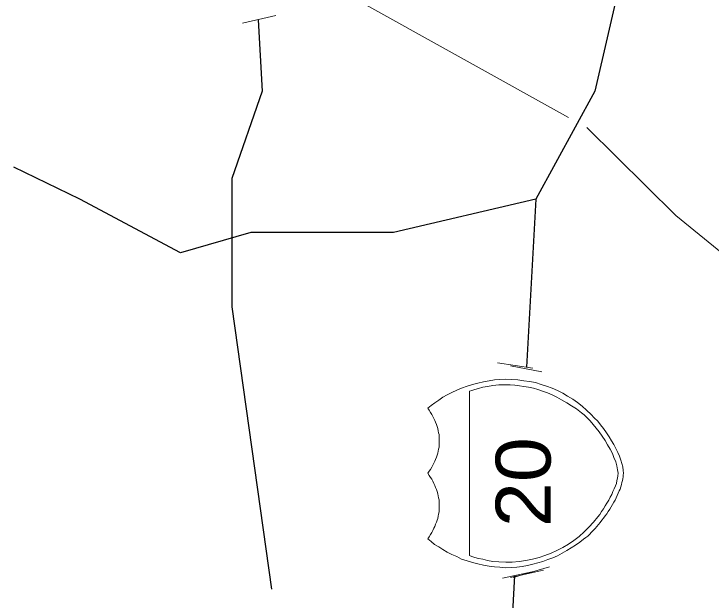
# Model space of a CAD drawing. Extents: x 2363323 to 2367082, y 6956018 to 6980837.
# Drawn here: x 2365996.5 to 2366061.2, y 6980473 to 6980527.4 of the extents above; entities that cross this region are included whole.
import ezdxf

# ---------------------------------------------------------------- set-up
doc = ezdxf.new("R2010")
doc.units = 0
doc.header["$LTSCALE"] = 4.1
doc.layers.add('62', color=7, linetype='Continuous', lineweight=13)
doc.layers.add('63', color=7, linetype='Continuous', lineweight=13)

msp = doc.modelspace()

# ---------------------------------------------------------------- linework, layer by layer
at = {"layer": '62'}
for p, q in [((2366026.698, 6980529.676), (2366047.962, 6980517.816)), ((2366017.744, 6980526.572), (2366020.826, 6980527.268)), ((2366041.396, 6980495.044), (2366044.656, 6980494.55)), ((2366042.586, 6980494.773), (2366045.489, 6980494.212)), ((2366041.846, 6980475.063), (2366044.612, 6980475.672)), ((2366042.588, 6980475.132), (2366045.67, 6980475.828)), ((2366042.834, 6980475.13), (2366046.209, 6980476.12))]:
    msp.add_line(p, q, dxfattribs=at)
at = {"layer": '62', "lineweight": 25}
for p, q in [((2366002.646, 6980510.235), (2365996.546, 6980513.204)), ((2366044.949, 6980510.235), (2366044.073, 6980494.64))]:
    msp.add_line(p, q, dxfattribs=at)
for points in [[(2366048.01, 6980685.208), (2366049.539, 6980677.378), (2366050.418, 6980667.388), (2366051.476, 6980653.346), (2366051.474, 6980643.356), (2366052.352, 6980636.2), (2366055.164, 6980631.206), (2366057.122, 6980621.192), (2366056.064, 6980607.15), (2366055.164, 6980594.301), (2366054.309, 6980580.237), (2366057.123, 6980558.096), (2366054.309, 6980537.146), (2366050.416, 6980520.246), (2366044.949, 6980510.235), (2366031.738, 6980507.152), (2366018.51, 6980507.151), (2366011.984, 6980505.261), (2366002.646, 6980510.235)], [(2366019.184, 6980526.885), (2366019.568, 6980520.246), (2366016.755, 6980512.146), (2366016.754, 6980500.244), (2366020.445, 6980474.05)], [(2366042.97, 6980475.31), (2366042.183, 6980460.999), (2366034.551, 6980446.35), (2366022.334, 6980438.454)]]:
    msp.add_lwpolyline(points, dxfattribs=at)
at = {"layer": '62'}
for points in [[(2366049.676, 6980516.892), (2366057.932, 6980508.726), (2366065.266, 6980502.741), (2366077.871, 6980489.824), (2366091.302, 6980478.192)], [(2366035.408, 6980485.548), (2366035.498, 6980485.728), (2366035.588, 6980485.93), (2366035.655, 6980486.088), (2366035.745, 6980486.292), (2366035.79, 6980486.493), (2366035.859, 6980486.673), (2366035.88, 6980486.853), (2366035.925, 6980487.054), (2366035.972, 6980487.236), (2366035.994, 6980487.436), (2366035.994, 6980487.618), (2366035.992, 6980487.822), (2366035.992, 6980488.002), (2366035.992, 6980488.182), (2366035.97, 6980488.407), (2366035.926, 6980488.564), (2366035.88, 6980488.744), (2366035.858, 6980488.948), (2366035.79, 6980489.15), (2366035.745, 6980489.331), (2366035.656, 6980489.532), (2366035.589, 6980489.712), (2366035.499, 6980489.89), (2366035.408, 6980490.074), (2366035.294, 6980490.252), (2366035.182, 6980490.454), (2366035.068, 6980490.658), (2366034.934, 6980490.838), (2366035.248, 6980491.107), (2366035.566, 6980491.354), (2366035.948, 6980491.602), (2366036.33, 6980491.85), (2366036.738, 6980492.073), (2366037.164, 6980492.3), (2366037.614, 6980492.502), (2366038.064, 6980492.704), (2366038.582, 6980492.884), (2366039.076, 6980493.04), (2366039.573, 6980493.178), (2366040.089, 6980493.29), (2366040.608, 6980493.38), (2366041.124, 6980493.47), (2366041.619, 6980493.492), (2366042.159, 6980493.537), (2366042.7, 6980493.492), (2366043.284, 6980493.47), (2366043.826, 6980493.38), (2366044.364, 6980493.312), (2366044.904, 6980493.224), (2366045.444, 6980493.042), (2366045.939, 6980492.884), (2366046.456, 6980492.704), (2366046.953, 6980492.48), (2366047.446, 6980492.232), (2366047.896, 6980491.964), (2366048.37, 6980491.692), (2366048.82, 6980491.356), (2366049.246, 6980491.017), (2366049.652, 6980490.657), (2366050.079, 6980490.252), (2366050.372, 6980489.96), (2366050.686, 6980489.644), (2366050.956, 6980489.284), (2366051.226, 6980488.948), (2366051.496, 6980488.564), (2366051.744, 6980488.18), (2366051.97, 6980487.822), (2366052.196, 6980487.46), (2366052.374, 6980487.1), (2366052.554, 6980486.74), (2366052.712, 6980486.38), (2366052.846, 6980486.022), (2366052.914, 6980485.706), (2366053.006, 6980485.39), (2366053.049, 6980485.076), (2366053.072, 6980484.807)], [(2366053.072, 6980484.807), (2366053.05, 6980484.624), (2366053.05, 6980484.468), (2366053.004, 6980484.288), (2366052.982, 6980484.132), (2366052.936, 6980483.95), (2366052.892, 6980483.77), (2366052.824, 6980483.546), (2366052.756, 6980483.343), (2366052.668, 6980483.164), (2366052.578, 6980482.96), (2366052.486, 6980482.736), (2366052.396, 6980482.533), (2366052.306, 6980482.308), (2366052.196, 6980482.13), (2366052.06, 6980481.903), (2366051.946, 6980481.678), (2366051.812, 6980481.476), (2366051.654, 6980481.25), (2366051.52, 6980481.05), (2366051.386, 6980480.847), (2366051.228, 6980480.643), (2366051.069, 6980480.442), (2366050.913, 6980480.238), (2366050.756, 6980480.058), (2366050.596, 6980479.856), (2366050.439, 6980479.676), (2366050.259, 6980479.496), (2366050.102, 6980479.338), (2366049.922, 6980479.136), (2366049.766, 6980478.978), (2366049.584, 6980478.843), (2366049.382, 6980478.686), (2366049.022, 6980478.414), (2366048.616, 6980478.123), (2366048.213, 6980477.876), (2366047.808, 6980477.628), (2366047.38, 6980477.382), (2366046.953, 6980477.156), (2366046.524, 6980476.954), (2366046.052, 6980476.796), (2366045.602, 6980476.616), (2366045.13, 6980476.48), (2366044.656, 6980476.368), (2366044.184, 6980476.256), (2366043.689, 6980476.143), (2366043.196, 6980476.098), (2366042.654, 6980476.052), (2366042.16, 6980476.032), (2366041.618, 6980476.076), (2366041.124, 6980476.122), (2366040.606, 6980476.188), (2366040.089, 6980476.28), (2366039.573, 6980476.39), (2366039.076, 6980476.524), (2366038.582, 6980476.682), (2366038.064, 6980476.842), (2366037.616, 6980477.066), (2366037.164, 6980477.27), (2366036.738, 6980477.493), (2366036.33, 6980477.718), (2366035.948, 6980477.986), (2366035.565, 6980478.19), (2366035.25, 6980478.459), (2366034.934, 6980478.73), (2366035.068, 6980478.91), (2366035.182, 6980479.113), (2366035.294, 6980479.316), (2366035.408, 6980479.497), (2366035.498, 6980479.698), (2366035.588, 6980479.878), (2366035.656, 6980480.08), (2366035.745, 6980480.262), (2366035.79, 6980480.44), (2366035.858, 6980480.62), (2366035.88, 6980480.823), (2366035.926, 6980481.003), (2366035.97, 6980481.23), (2366035.992, 6980481.386), (2366035.992, 6980481.566), (2366035.994, 6980481.792), (2366035.992, 6980481.972), (2366035.994, 6980482.149), (2366035.972, 6980482.353), (2366035.926, 6980482.533), (2366035.882, 6980482.712), (2366035.858, 6980482.893), (2366035.792, 6980483.12), (2366035.746, 6980483.3), (2366035.655, 6980483.478), (2366035.589, 6980483.658), (2366035.498, 6980483.86), (2366035.408, 6980484.063), (2366035.294, 6980484.244), (2366035.181, 6980484.423), (2366035.07, 6980484.603), (2366034.934, 6980484.806), (2366035.07, 6980484.986), (2366035.182, 6980485.166), (2366035.295, 6980485.368), (2366035.408, 6980485.548)]]:
    msp.add_lwpolyline(points, dxfattribs=at)
msp.add_lwpolyline([(2366038.786, 6980492.412), (2366038.786, 6980477.178), (2366039.01, 6980477.088), (2366039.302, 6980476.998), (2366039.618, 6980476.908), (2366040.023, 6980476.82), (2366040.473, 6980476.706), (2366040.966, 6980476.616), (2366041.53, 6980476.572), (2366042.16, 6980476.57), (2366042.768, 6980476.57), (2366043.396, 6980476.616), (2366044.026, 6980476.704), (2366044.634, 6980476.842), (2366045.242, 6980476.998), (2366045.783, 6980477.178), (2366046.366, 6980477.382), (2366046.908, 6980477.652), (2366047.446, 6980477.92), (2366047.964, 6980478.213), (2366048.483, 6980478.573), (2366048.956, 6980478.933), (2366049.426, 6980479.36), (2366049.876, 6980479.81), (2366050.283, 6980480.26), (2366050.688, 6980480.756), (2366050.89, 6980480.98), (2366051.046, 6980481.25), (2366051.228, 6980481.498), (2366051.386, 6980481.789), (2366051.542, 6980482.038), (2366051.723, 6980482.308), (2366051.856, 6980482.58), (2366051.992, 6980482.848), (2366052.104, 6980483.118), (2366052.216, 6980483.366), (2366052.33, 6980483.637), (2366052.419, 6980483.86), (2366052.464, 6980484.13), (2366052.533, 6980484.354), (2366052.556, 6980484.58), (2366052.576, 6980484.807), (2366052.533, 6980485.12), (2366052.464, 6980485.503), (2366052.353, 6980485.864), (2366052.196, 6980486.268), (2366052.06, 6980486.65), (2366051.834, 6980487.054), (2366051.609, 6980487.438), (2366051.386, 6980487.844), (2366051.114, 6980488.25), (2366050.822, 6980488.634), (2366050.553, 6980488.992), (2366050.259, 6980489.33), (2366049.989, 6980489.668), (2366049.72, 6980489.96), (2366049.426, 6980490.23), (2366049.179, 6980490.41), (2366048.706, 6980490.77), (2366048.256, 6980491.062), (2366047.808, 6980491.354), (2366047.336, 6980491.623), (2366046.908, 6980491.874), (2366046.456, 6980492.076), (2366046.03, 6980492.254), (2366045.58, 6980492.414), (2366045.13, 6980492.57), (2366044.726, 6980492.704), (2366044.274, 6980492.794), (2366043.846, 6980492.862), (2366043.419, 6980492.93), (2366042.992, 6980492.974), (2366042.566, 6980492.997), (2366042.159, 6980492.997), (2366041.53, 6980492.997), (2366040.966, 6980492.952), (2366040.473, 6980492.862), (2366040.023, 6980492.794), (2366039.618, 6980492.682), (2366039.303, 6980492.57), (2366039.009, 6980492.48)], close=True, dxfattribs=at)
at = {"layer": '63'}
for p, q in [((2366026.698, 6980529.676), (2366047.962, 6980517.816)), ((2366017.744, 6980526.572), (2366020.826, 6980527.268)), ((2366041.396, 6980495.044), (2366044.656, 6980494.55)), ((2366042.586, 6980494.773), (2366045.489, 6980494.212)), ((2366041.846, 6980475.063), (2366044.612, 6980475.672)), ((2366042.588, 6980475.132), (2366045.67, 6980475.828)), ((2366042.834, 6980475.13), (2366046.209, 6980476.12))]:
    msp.add_line(p, q, dxfattribs=at)
at = {"layer": '63', "lineweight": 25}
for p, q in [((2366002.646, 6980510.235), (2365996.546, 6980513.204)), ((2366044.949, 6980510.235), (2366044.073, 6980494.64))]:
    msp.add_line(p, q, dxfattribs=at)
for points in [[(2366048.01, 6980685.208), (2366049.539, 6980677.378), (2366050.418, 6980667.388), (2366051.476, 6980653.346), (2366051.474, 6980643.356), (2366052.352, 6980636.2), (2366055.164, 6980631.206), (2366057.122, 6980621.192), (2366056.064, 6980607.15), (2366055.164, 6980594.301), (2366054.309, 6980580.237), (2366057.123, 6980558.096), (2366054.309, 6980537.146), (2366050.416, 6980520.246), (2366044.949, 6980510.235), (2366031.738, 6980507.152), (2366018.51, 6980507.151), (2366011.984, 6980505.261), (2366002.646, 6980510.235)], [(2366019.184, 6980526.885), (2366019.568, 6980520.246), (2366016.755, 6980512.146), (2366016.754, 6980500.244), (2366020.445, 6980474.05)], [(2366042.97, 6980475.31), (2366042.183, 6980460.999), (2366034.551, 6980446.35), (2366022.334, 6980438.454)]]:
    msp.add_lwpolyline(points, dxfattribs=at)
at = {"layer": '63'}
for points in [[(2366049.676, 6980516.892), (2366057.932, 6980508.726), (2366065.266, 6980502.741), (2366077.871, 6980489.824), (2366091.302, 6980478.192)], [(2366035.408, 6980485.548), (2366035.498, 6980485.728), (2366035.588, 6980485.93), (2366035.655, 6980486.088), (2366035.745, 6980486.292), (2366035.79, 6980486.493), (2366035.859, 6980486.673), (2366035.88, 6980486.853), (2366035.925, 6980487.054), (2366035.972, 6980487.236), (2366035.994, 6980487.436), (2366035.994, 6980487.618), (2366035.992, 6980487.822), (2366035.992, 6980488.002), (2366035.992, 6980488.182), (2366035.97, 6980488.407), (2366035.926, 6980488.564), (2366035.88, 6980488.744), (2366035.858, 6980488.948), (2366035.79, 6980489.15), (2366035.745, 6980489.331), (2366035.656, 6980489.532), (2366035.589, 6980489.712), (2366035.499, 6980489.89), (2366035.408, 6980490.074), (2366035.294, 6980490.252), (2366035.182, 6980490.454), (2366035.068, 6980490.658), (2366034.934, 6980490.838), (2366035.248, 6980491.107), (2366035.566, 6980491.354), (2366035.948, 6980491.602), (2366036.33, 6980491.85), (2366036.738, 6980492.073), (2366037.164, 6980492.3), (2366037.614, 6980492.502), (2366038.064, 6980492.704), (2366038.582, 6980492.884), (2366039.076, 6980493.04), (2366039.573, 6980493.178), (2366040.089, 6980493.29), (2366040.608, 6980493.38), (2366041.124, 6980493.47), (2366041.619, 6980493.492), (2366042.159, 6980493.537), (2366042.7, 6980493.492), (2366043.284, 6980493.47), (2366043.826, 6980493.38), (2366044.364, 6980493.312), (2366044.904, 6980493.224), (2366045.444, 6980493.042), (2366045.939, 6980492.884), (2366046.456, 6980492.704), (2366046.953, 6980492.48), (2366047.446, 6980492.232), (2366047.896, 6980491.964), (2366048.37, 6980491.692), (2366048.82, 6980491.356), (2366049.246, 6980491.017), (2366049.652, 6980490.657), (2366050.079, 6980490.252), (2366050.372, 6980489.96), (2366050.686, 6980489.644), (2366050.956, 6980489.284), (2366051.226, 6980488.948), (2366051.496, 6980488.564), (2366051.744, 6980488.18), (2366051.97, 6980487.822), (2366052.196, 6980487.46), (2366052.374, 6980487.1), (2366052.554, 6980486.74), (2366052.712, 6980486.38), (2366052.846, 6980486.022), (2366052.914, 6980485.706), (2366053.006, 6980485.39), (2366053.049, 6980485.076), (2366053.072, 6980484.807)], [(2366053.072, 6980484.807), (2366053.05, 6980484.624), (2366053.05, 6980484.468), (2366053.004, 6980484.288), (2366052.982, 6980484.132), (2366052.936, 6980483.95), (2366052.892, 6980483.77), (2366052.824, 6980483.546), (2366052.756, 6980483.343), (2366052.668, 6980483.164), (2366052.578, 6980482.96), (2366052.486, 6980482.736), (2366052.396, 6980482.533), (2366052.306, 6980482.308), (2366052.196, 6980482.13), (2366052.06, 6980481.903), (2366051.946, 6980481.678), (2366051.812, 6980481.476), (2366051.654, 6980481.25), (2366051.52, 6980481.05), (2366051.386, 6980480.847), (2366051.228, 6980480.643), (2366051.069, 6980480.442), (2366050.913, 6980480.238), (2366050.756, 6980480.058), (2366050.596, 6980479.856), (2366050.439, 6980479.676), (2366050.259, 6980479.496), (2366050.102, 6980479.338), (2366049.922, 6980479.136), (2366049.766, 6980478.978), (2366049.584, 6980478.843), (2366049.382, 6980478.686), (2366049.022, 6980478.414), (2366048.616, 6980478.123), (2366048.213, 6980477.876), (2366047.808, 6980477.628), (2366047.38, 6980477.382), (2366046.953, 6980477.156), (2366046.524, 6980476.954), (2366046.052, 6980476.796), (2366045.602, 6980476.616), (2366045.13, 6980476.48), (2366044.656, 6980476.368), (2366044.184, 6980476.256), (2366043.689, 6980476.143), (2366043.196, 6980476.098), (2366042.654, 6980476.052), (2366042.16, 6980476.032), (2366041.618, 6980476.076), (2366041.124, 6980476.122), (2366040.606, 6980476.188), (2366040.089, 6980476.28), (2366039.573, 6980476.39), (2366039.076, 6980476.524), (2366038.582, 6980476.682), (2366038.064, 6980476.842), (2366037.616, 6980477.066), (2366037.164, 6980477.27), (2366036.738, 6980477.493), (2366036.33, 6980477.718), (2366035.948, 6980477.986), (2366035.565, 6980478.19), (2366035.25, 6980478.459), (2366034.934, 6980478.73), (2366035.068, 6980478.91), (2366035.182, 6980479.113), (2366035.294, 6980479.316), (2366035.408, 6980479.497), (2366035.498, 6980479.698), (2366035.588, 6980479.878), (2366035.656, 6980480.08), (2366035.745, 6980480.262), (2366035.79, 6980480.44), (2366035.858, 6980480.62), (2366035.88, 6980480.823), (2366035.926, 6980481.003), (2366035.97, 6980481.23), (2366035.992, 6980481.386), (2366035.992, 6980481.566), (2366035.994, 6980481.792), (2366035.992, 6980481.972), (2366035.994, 6980482.149), (2366035.972, 6980482.353), (2366035.926, 6980482.533), (2366035.882, 6980482.712), (2366035.858, 6980482.893), (2366035.792, 6980483.12), (2366035.746, 6980483.3), (2366035.655, 6980483.478), (2366035.589, 6980483.658), (2366035.498, 6980483.86), (2366035.408, 6980484.063), (2366035.294, 6980484.244), (2366035.181, 6980484.423), (2366035.07, 6980484.603), (2366034.934, 6980484.806), (2366035.07, 6980484.986), (2366035.182, 6980485.166), (2366035.295, 6980485.368), (2366035.408, 6980485.548)]]:
    msp.add_lwpolyline(points, dxfattribs=at)
msp.add_lwpolyline([(2366038.786, 6980492.412), (2366038.786, 6980477.178), (2366039.01, 6980477.088), (2366039.302, 6980476.998), (2366039.618, 6980476.908), (2366040.023, 6980476.82), (2366040.473, 6980476.706), (2366040.966, 6980476.616), (2366041.53, 6980476.572), (2366042.16, 6980476.57), (2366042.768, 6980476.57), (2366043.396, 6980476.616), (2366044.026, 6980476.704), (2366044.634, 6980476.842), (2366045.242, 6980476.998), (2366045.783, 6980477.178), (2366046.366, 6980477.382), (2366046.908, 6980477.652), (2366047.446, 6980477.92), (2366047.964, 6980478.213), (2366048.483, 6980478.573), (2366048.956, 6980478.933), (2366049.426, 6980479.36), (2366049.876, 6980479.81), (2366050.283, 6980480.26), (2366050.688, 6980480.756), (2366050.89, 6980480.98), (2366051.046, 6980481.25), (2366051.228, 6980481.498), (2366051.386, 6980481.789), (2366051.542, 6980482.038), (2366051.723, 6980482.308), (2366051.856, 6980482.58), (2366051.992, 6980482.848), (2366052.104, 6980483.118), (2366052.216, 6980483.366), (2366052.33, 6980483.637), (2366052.419, 6980483.86), (2366052.464, 6980484.13), (2366052.533, 6980484.354), (2366052.556, 6980484.58), (2366052.576, 6980484.807), (2366052.533, 6980485.12), (2366052.464, 6980485.503), (2366052.353, 6980485.864), (2366052.196, 6980486.268), (2366052.06, 6980486.65), (2366051.834, 6980487.054), (2366051.609, 6980487.438), (2366051.386, 6980487.844), (2366051.114, 6980488.25), (2366050.822, 6980488.634), (2366050.553, 6980488.992), (2366050.259, 6980489.33), (2366049.989, 6980489.668), (2366049.72, 6980489.96), (2366049.426, 6980490.23), (2366049.179, 6980490.41), (2366048.706, 6980490.77), (2366048.256, 6980491.062), (2366047.808, 6980491.354), (2366047.336, 6980491.623), (2366046.908, 6980491.874), (2366046.456, 6980492.076), (2366046.03, 6980492.254), (2366045.58, 6980492.414), (2366045.13, 6980492.57), (2366044.726, 6980492.704), (2366044.274, 6980492.794), (2366043.846, 6980492.862), (2366043.419, 6980492.93), (2366042.992, 6980492.974), (2366042.566, 6980492.997), (2366042.159, 6980492.997), (2366041.53, 6980492.997), (2366040.966, 6980492.952), (2366040.473, 6980492.862), (2366040.023, 6980492.794), (2366039.618, 6980492.682), (2366039.303, 6980492.57), (2366039.009, 6980492.48)], close=True, dxfattribs=at)

# ---------------------------------------------------------------- texts
at = {"layer": '62', "width": 1.1}
msp.add_text('20', height=5.099, rotation=90, dxfattribs=at).set_placement((2366046.321, 6980479.81))
at = {"layer": '63', "width": 1.1}
msp.add_text('20', height=5.099, rotation=90, dxfattribs=at).set_placement((2366046.321, 6980479.81))

doc.saveas('drawing.dxf')
